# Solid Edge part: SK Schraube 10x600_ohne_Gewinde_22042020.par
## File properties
Author: fknapp
Template: Normal.par
Last saved by: fknapp
Revision: 38
Application: Solid Edge
Username: fknapp
Material: Aluminium
Genauigkeit: 0,99
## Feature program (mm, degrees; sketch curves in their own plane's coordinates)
sketch for "unnamed RevolvedProtrusion 1" plane through (0, 0, 0) normal (0, 0, 1) x-axis (1, 0, 0)
  line (0, 54) -> (9, 54)
  line (9, 54) -> (9, 53)
  line (9, 53) -> (5, 49)
  line (5, 49) -> (5, 46.3)
  line (5, 46.3) -> (4.7548, 46.3)
  arc centre (4.7548, 44.6952) radius 1.6048 from (4.7548, 46.3) to (3.15, 44.6952) ccw
  line (3.15, 44.6952) -> (3.15, 42)
  line (3.15, 42) -> (5, 42)
  line (5, -533) -> (5, 42)
  line (0.5, -546) -> (5, -533)
  line (0, -546) -> (0.5, -546)
revolve "unnamed RevolvedProtrusion 1" add full turn 360 deg about sketch line (0, 54) -> (0, -546)
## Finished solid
Body 1: solid body, 11 faces, 10 edges, 0 vertices.
  Faces by surface: cylinder 4, plane 4, cone 2, torus 1
  Edges by curve: circle 10
Bounding box of the edges (mm; curved faces can reach further): 18.000 x 600.000 x 18.000, from (-9, -546, -9) to (9, 54, 9).
Cylindrical faces by radius (mm): R3.15 x1, R5 x2, R9 x1
Conical faces (half-angle, radius in mm at the cone's reference point): 19.0935 deg R5 x1, 45 deg R9 x1
Toroidal faces (ring radius, tube radius in mm): R4.7548 r1.6048 x1
Planar faces by outward normal: +y 2, -y 2
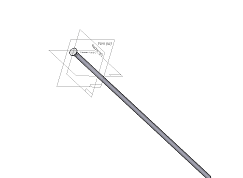
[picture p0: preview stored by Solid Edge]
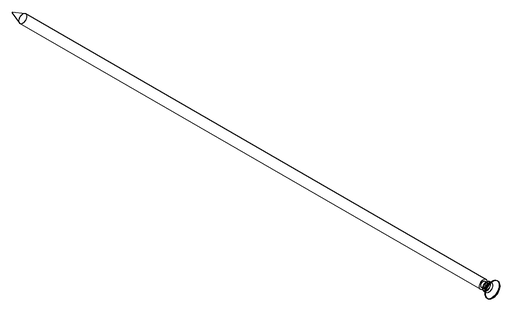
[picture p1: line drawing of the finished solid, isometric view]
